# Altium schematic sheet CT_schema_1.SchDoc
size 479 x 258 mm
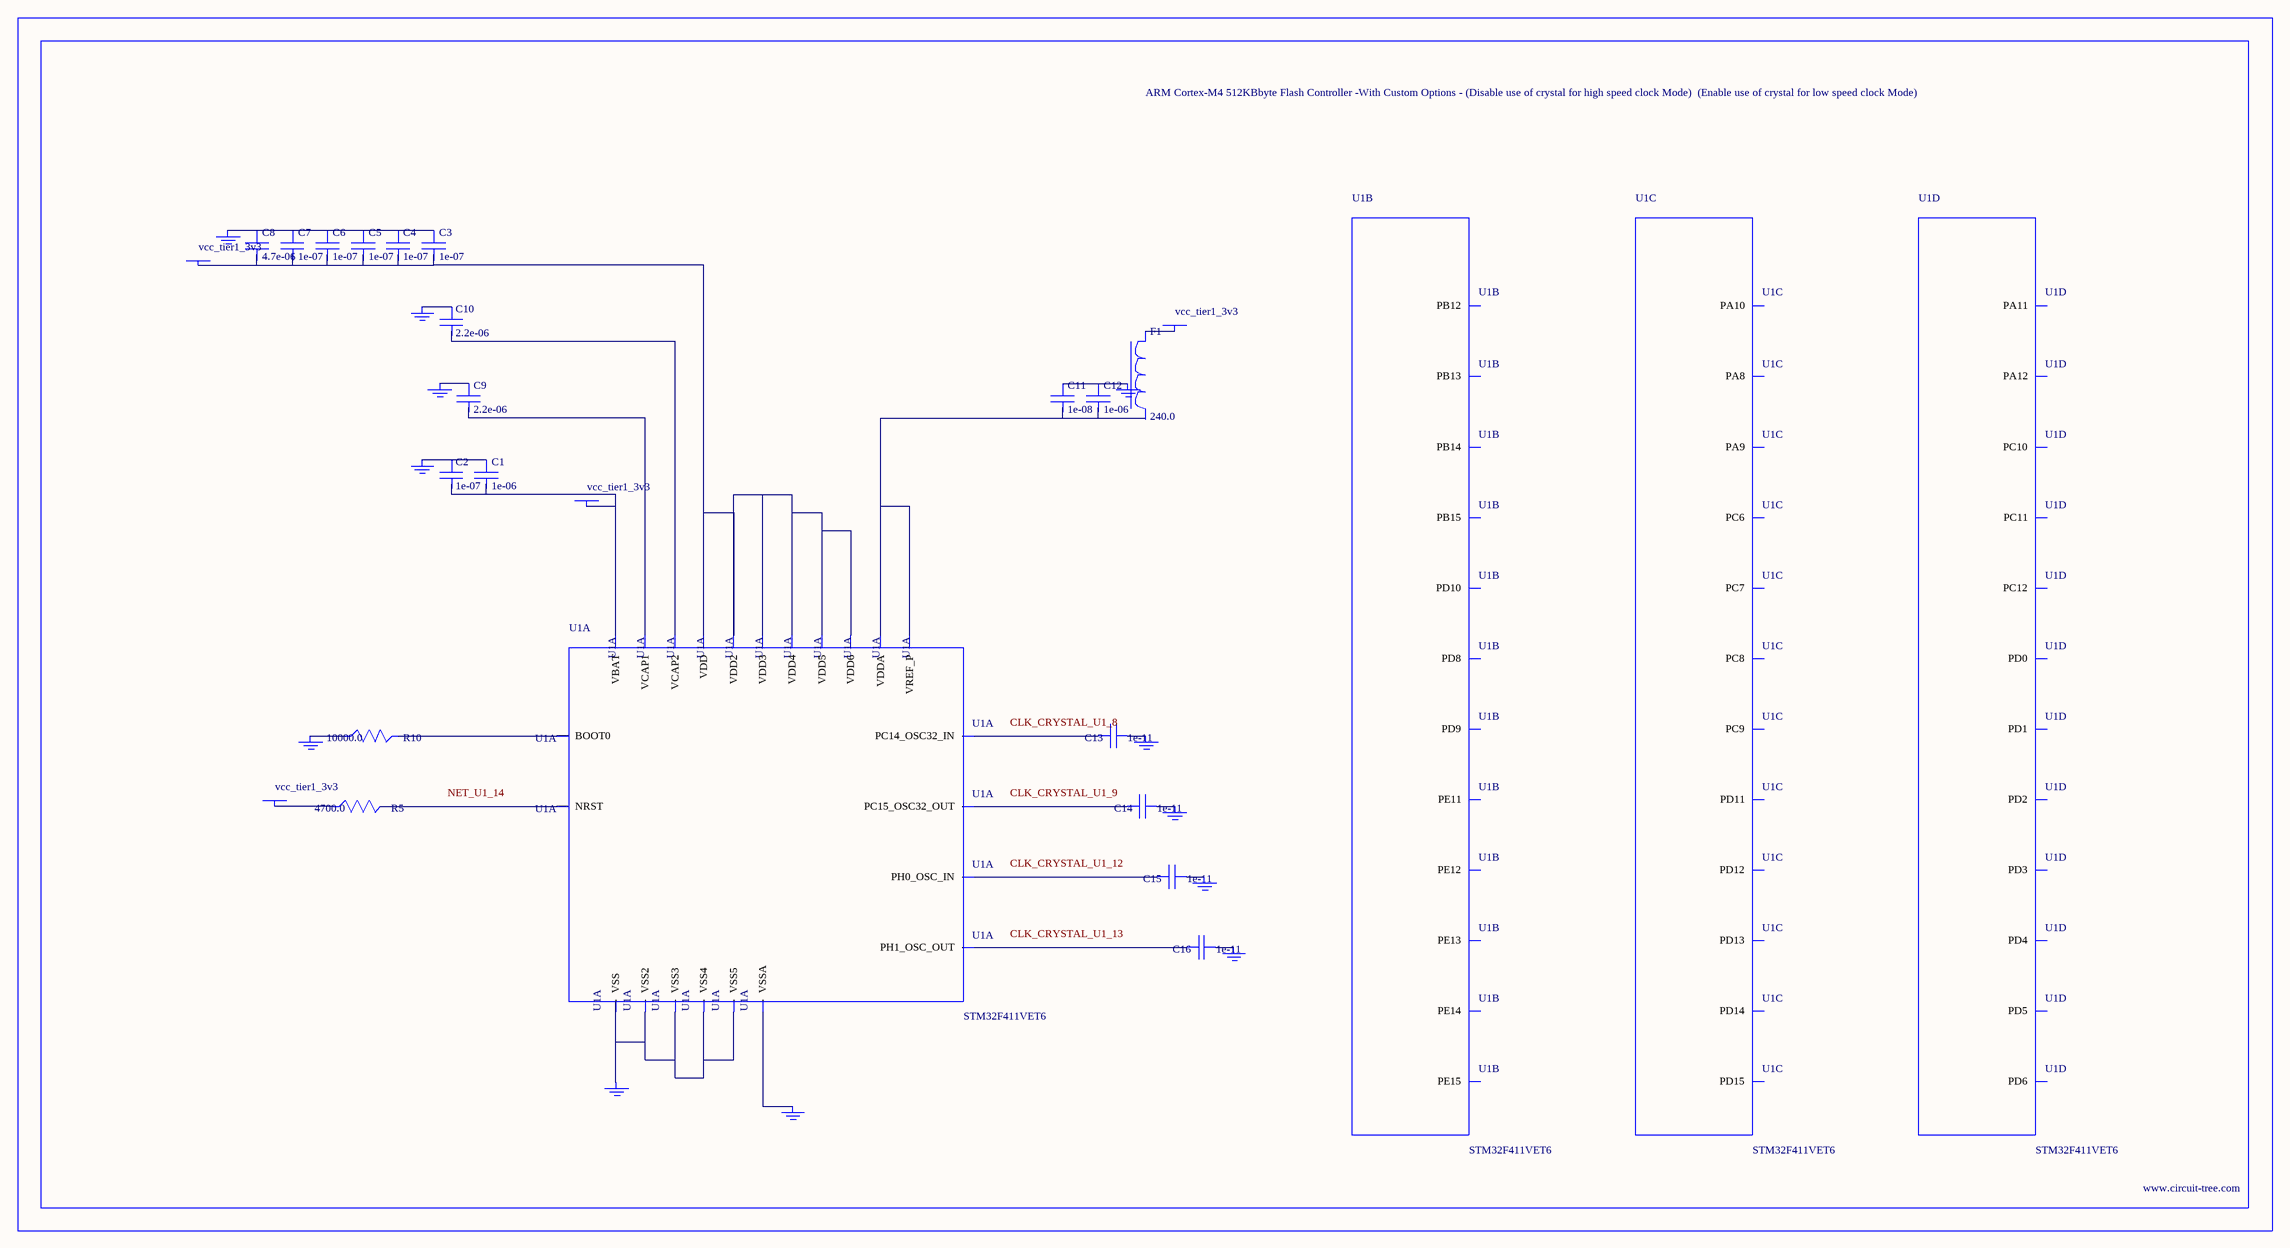
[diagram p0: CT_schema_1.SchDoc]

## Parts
BORDER0  (no value)
C1  1e-06  [C0603]
C2  1e-07  [C0603]
C3  1e-07  [C0603]
C4  1e-07  [C0603]
C5  1e-07  [C0603]
C6  1e-07  [C0603]
C7  1e-07  [C0603]
C8  4.7e-06  [C0603]
C9  2.2e-06  [C0603]
C10  2.2e-06  [C0603]
C11  1e-08  [C0603]
C12  1e-06  [C0603]
C13  1e-11  [C0402]
C14  1e-11  [C0402]
C15  1e-11  [C0402]
C16  1e-11  [C0402]
F1  240.0  [L0603]
GND_INSTANCE_0_0  (no value)
GND_INSTANCE_0_1  (no value)
GND_INSTANCE_0_2  (no value)
GND_INSTANCE_0_3  (no value)
GND_INSTANCE_0_4  (no value)
GND_INSTANCE_0_5  (no value)
GND_INSTANCE_0_6  (no value)
GND_INSTANCE_0_7  (no value)
GND_INSTANCE_0_8  (no value)
GND_INSTANCE_0_9  (no value)
GND_INSTANCE_0_10  (no value)
GND_INSTANCE_0_11  (no value)
POWER_INSTANCE_0_0  vcc_tier1_3v3
POWER_INSTANCE_0_1  vcc_tier1_3v3
POWER_INSTANCE_0_2  vcc_tier1_3v3
POWER_INSTANCE_0_3  vcc_tier1_3v3
R5  4700.0  [R0603]
R10  10000.0  [R0603]
U1  STM32F411VET6  [LQFP100]  (parts A,B,C,D of 10)

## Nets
NetC1_1: C1.1 C2.1 GND_INSTANCE_0_0.0(GND)
NetC1_2: C1.2 C2.2 POWER_INSTANCE_0_0.0(PWR) U1.6(VBAT)
NetC3_1: C3.1 C4.1 C5.1 C6.1 C7.1 C8.1 GND_INSTANCE_0_3.0(GND)
NetC3_2: C3.2 C4.2 C5.2 C6.2 C7.2 C8.2 POWER_INSTANCE_0_1.0(PWR) U1.11(VDD) U1.19(VDD2) U1.28(VDD3) U1.50(VDD4) U1.75(VDD5) U1.100(VDD6)
NetC9_1: C9.1 GND_INSTANCE_0_8.0(GND)
NetC9_2: C9.2 U1.48(VCAP1)
NetC10_1: C10.1 GND_INSTANCE_0_9.0(GND)
NetC10_2: C10.2 U1.73(VCAP2)
NetC11_1: C11.1 C12.1 GND_INSTANCE_0_7.0(GND)
NetC11_2: C11.2 C12.2 U1.21(VREF_P) U1.22(VDDA)
NetC13_1: C13.1 GND_INSTANCE_0_1.0(GND)
NetC13_2: C13.2 U1.8(PC14_OSC32_IN)
NetC14_1: C14.1 GND_INSTANCE_0_2.0(GND)
NetC14_2: C14.2 U1.9(PC15_OSC32_OUT)
NetC15_1: C15.1 GND_INSTANCE_0_4.0(GND)
NetC15_2: C15.2 U1.12(PH0_OSC_IN)
NetC16_1: C16.1 GND_INSTANCE_0_5.0(GND)
NetC16_2: C16.2 U1.13(PH1_OSC_OUT)
NetF1_1: F1.1 POWER_INSTANCE_0_2.0(PWR)
NetGND_INSTANCE_0_6_0: GND_INSTANCE_0_6.0(GND) U1.20(VSSA)
NetGND_INSTANCE_0_10_0: GND_INSTANCE_0_10.0(GND) R10.1
NetGND_INSTANCE_0_11_0: GND_INSTANCE_0_11.0(GND) U1.10(VSS) U1.27(VSS2) U1.49(VSS3) U1.74(VSS4) U1.99(VSS5)
NetPOWER_INSTANCE_0_3_0: POWER_INSTANCE_0_3.0(PWR) R5.1
NetR5_2: R5.2 U1.14(NRST)
NetR10_2: R10.2 U1.94(BOOT0)

Not connected (* = marked no-connect by the designer): F1 2; U1 42(PE11) 43(PE12) 44(PE13) 45(PE14) 46(PE15) 51(PB12) 52(PB13) 53(PB14) 54(PB15) 55(PD8) 56(PD9) 57(PD10) 58(PD11) 59(PD12) 60(PD13) 61(PD14) 62(PD15) 63(PC6) 64(PC7) 65(PC8) 66(PC9) 67(PA8) 68(PA9) 69(PA10) 70(PA11) 71(PA12) 78(PC10) 79(PC11) 80(PC12) 81(PD0) 82(PD1) 83(PD2) 84(PD3) 85(PD4) 86(PD5) 87(PD6)

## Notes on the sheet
- Labels drawn without touching a wire or pin: CLK_CRYSTAL_U1_8, CLK_CRYSTAL_U1_9, CLK_CRYSTAL_U1_12, CLK_CRYSTAL_U1_13, NET_U1_14

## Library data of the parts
BORDER0 = BORDER_PAGE0
C1 C12 = C0603C105K3RACTU
C2-C7 = 06035C104K4Z2A
C8 = GRM188R6YA475KE15D
C9 C10 = C0603C225K8RACTU
C11 = 06035C103K4Z2A
C13-C16 = C0402C100K3GACTU
F1 = Z0603C241ASMST
GND_INSTANCE_0_0-GND_INSTANCE_0_11 = GND
POWER_INSTANCE_0_0-POWER_INSTANCE_0_3 = PWR
R5 = RC0603JR-074K7L
R10 = RC0603JR-0710KL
